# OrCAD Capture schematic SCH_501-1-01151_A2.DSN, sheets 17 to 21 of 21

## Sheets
17 P17_USB-UART_USB2ANY_JTAG: size A3
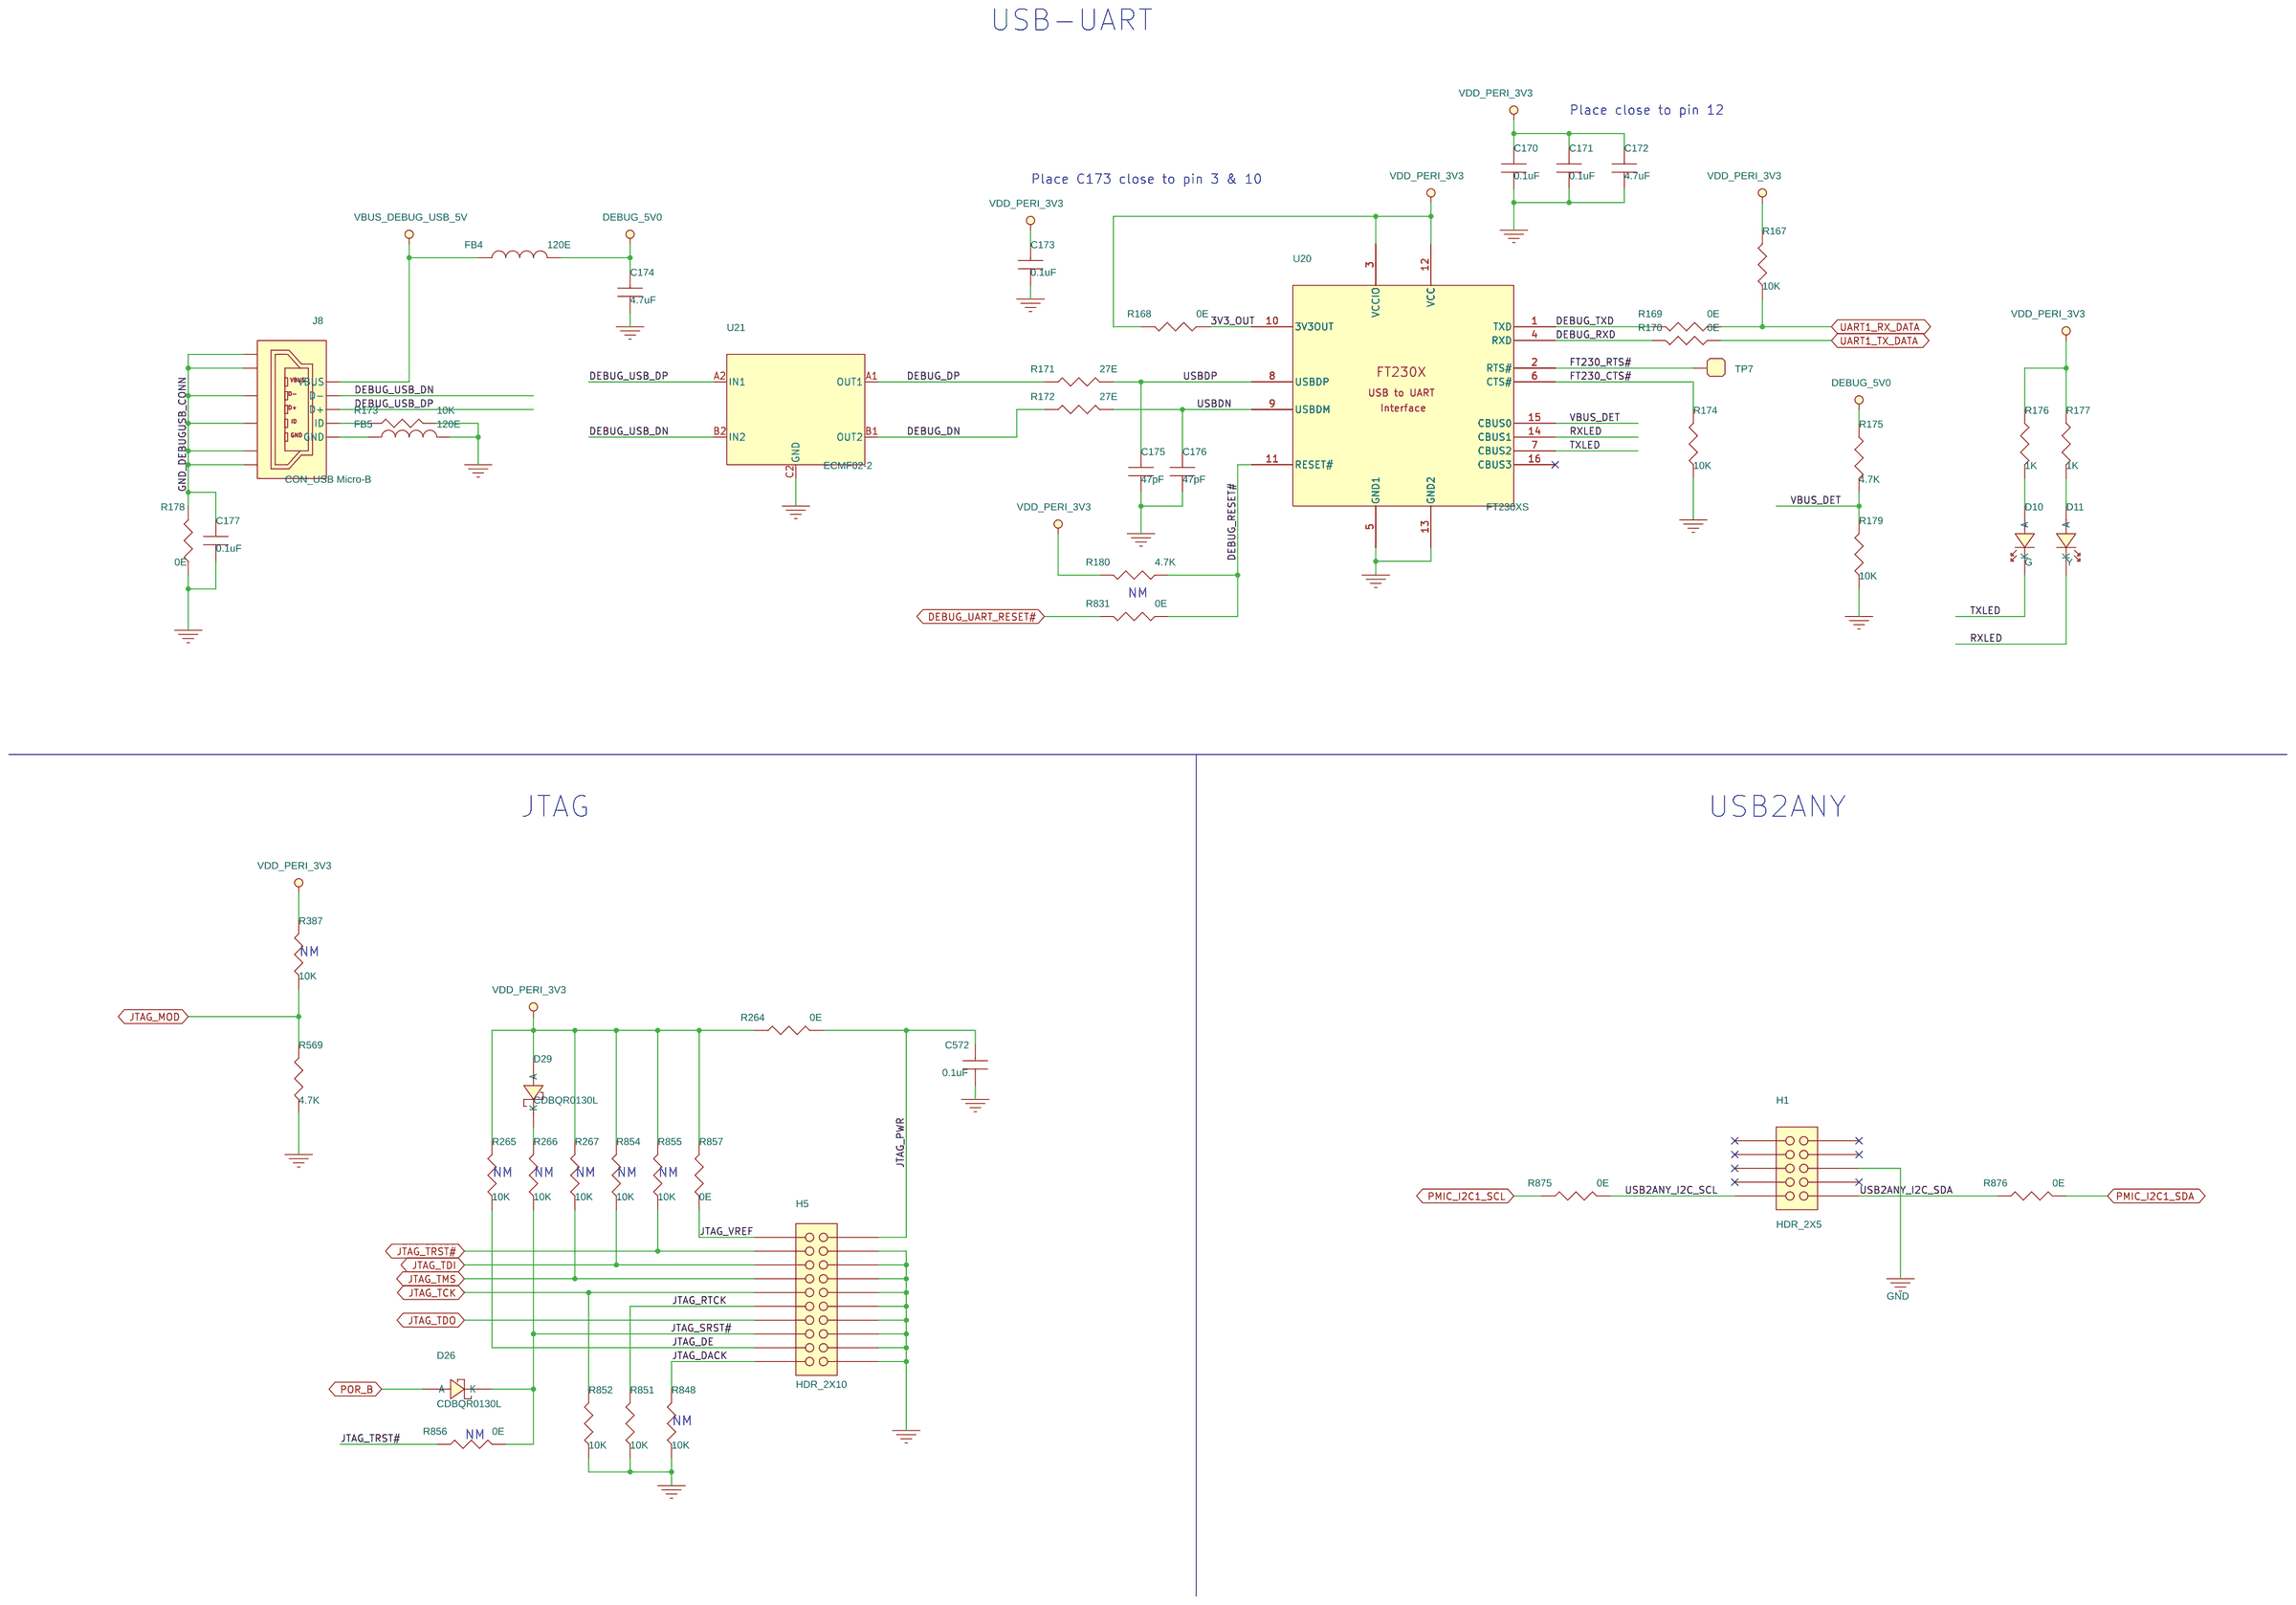
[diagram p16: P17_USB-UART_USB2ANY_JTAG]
18 P18_CURRENT SENSE: size A3
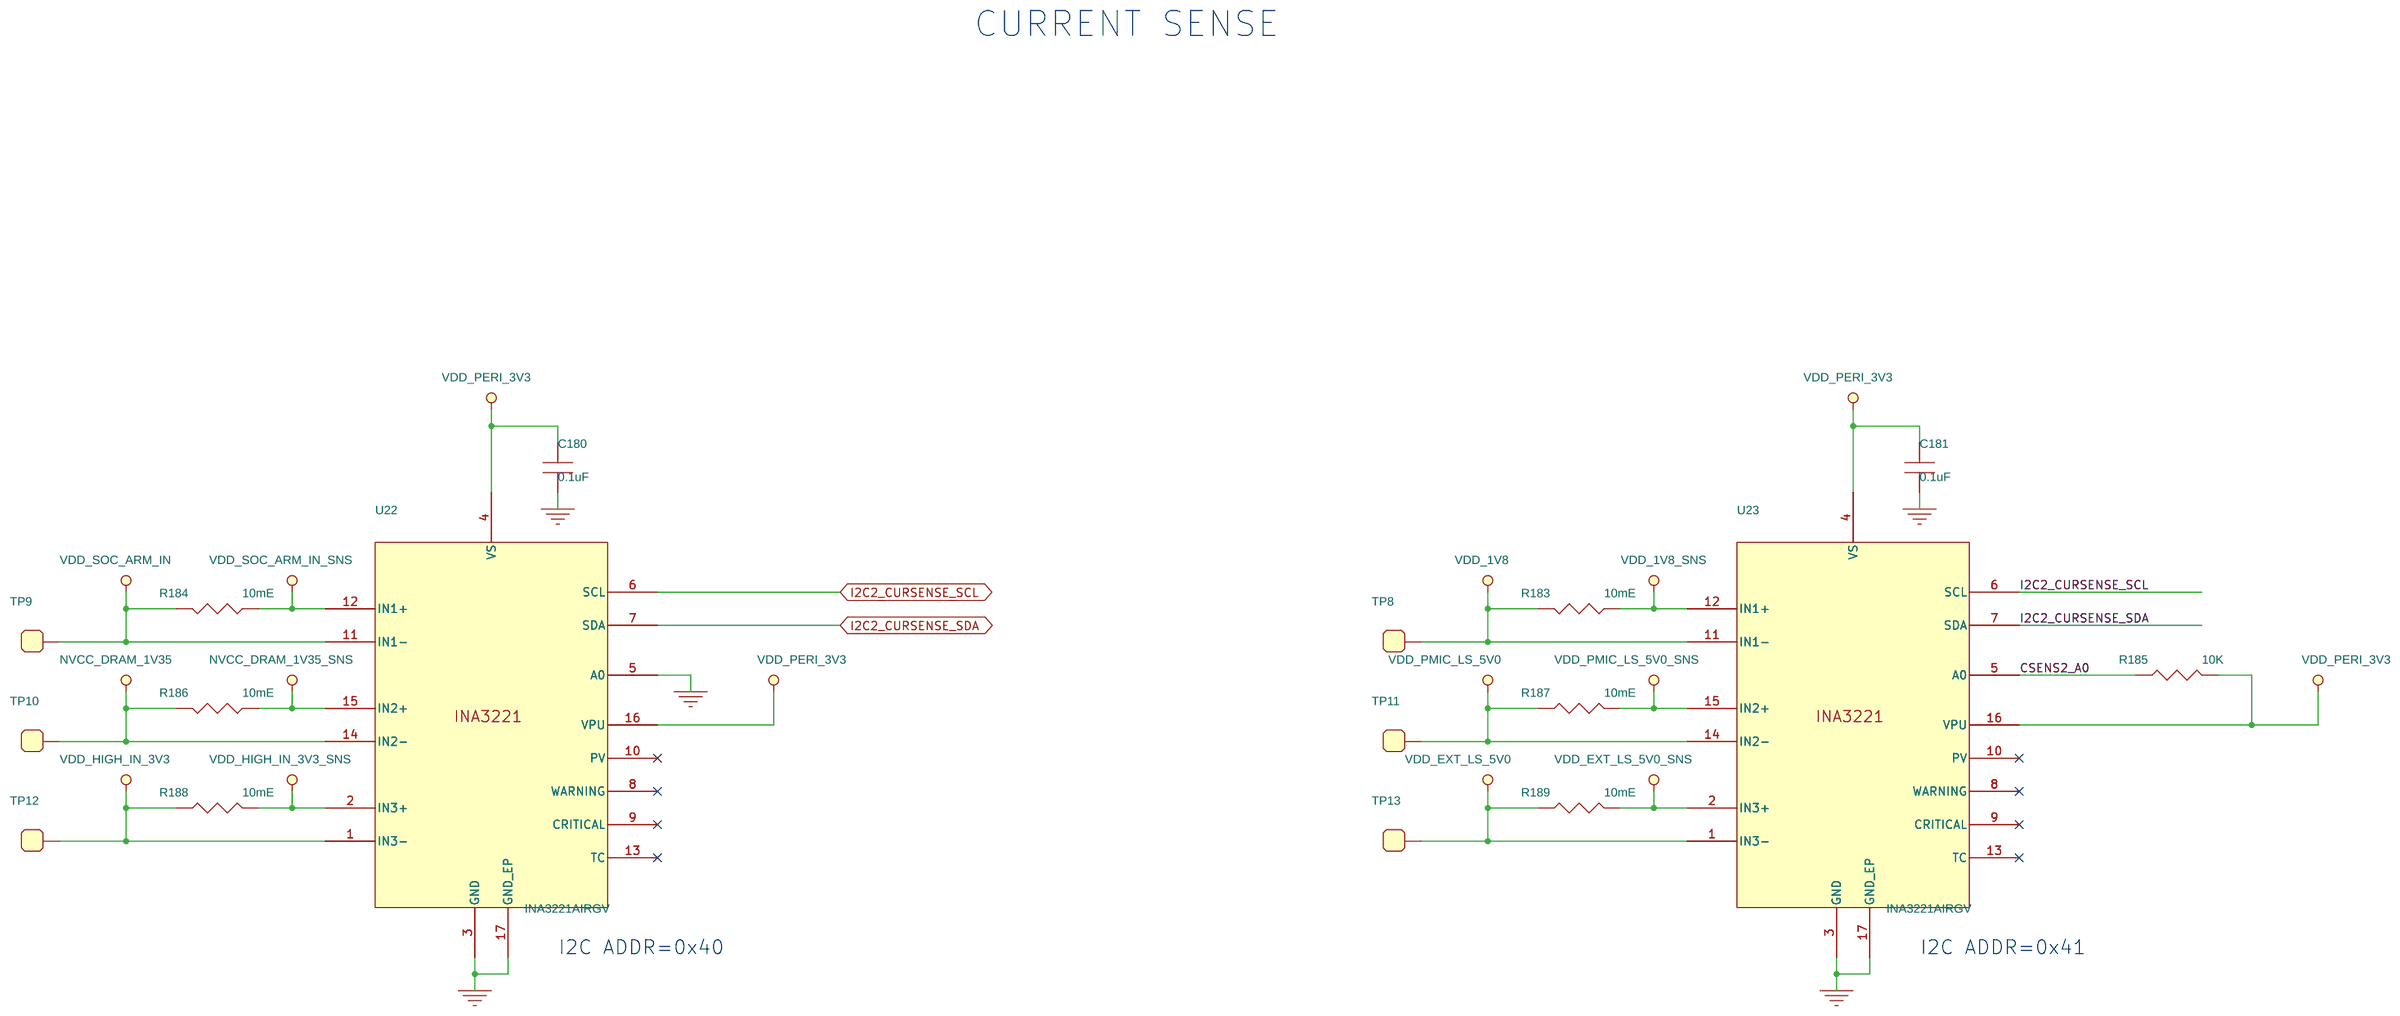
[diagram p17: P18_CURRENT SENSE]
19 P19_LCD: size A3
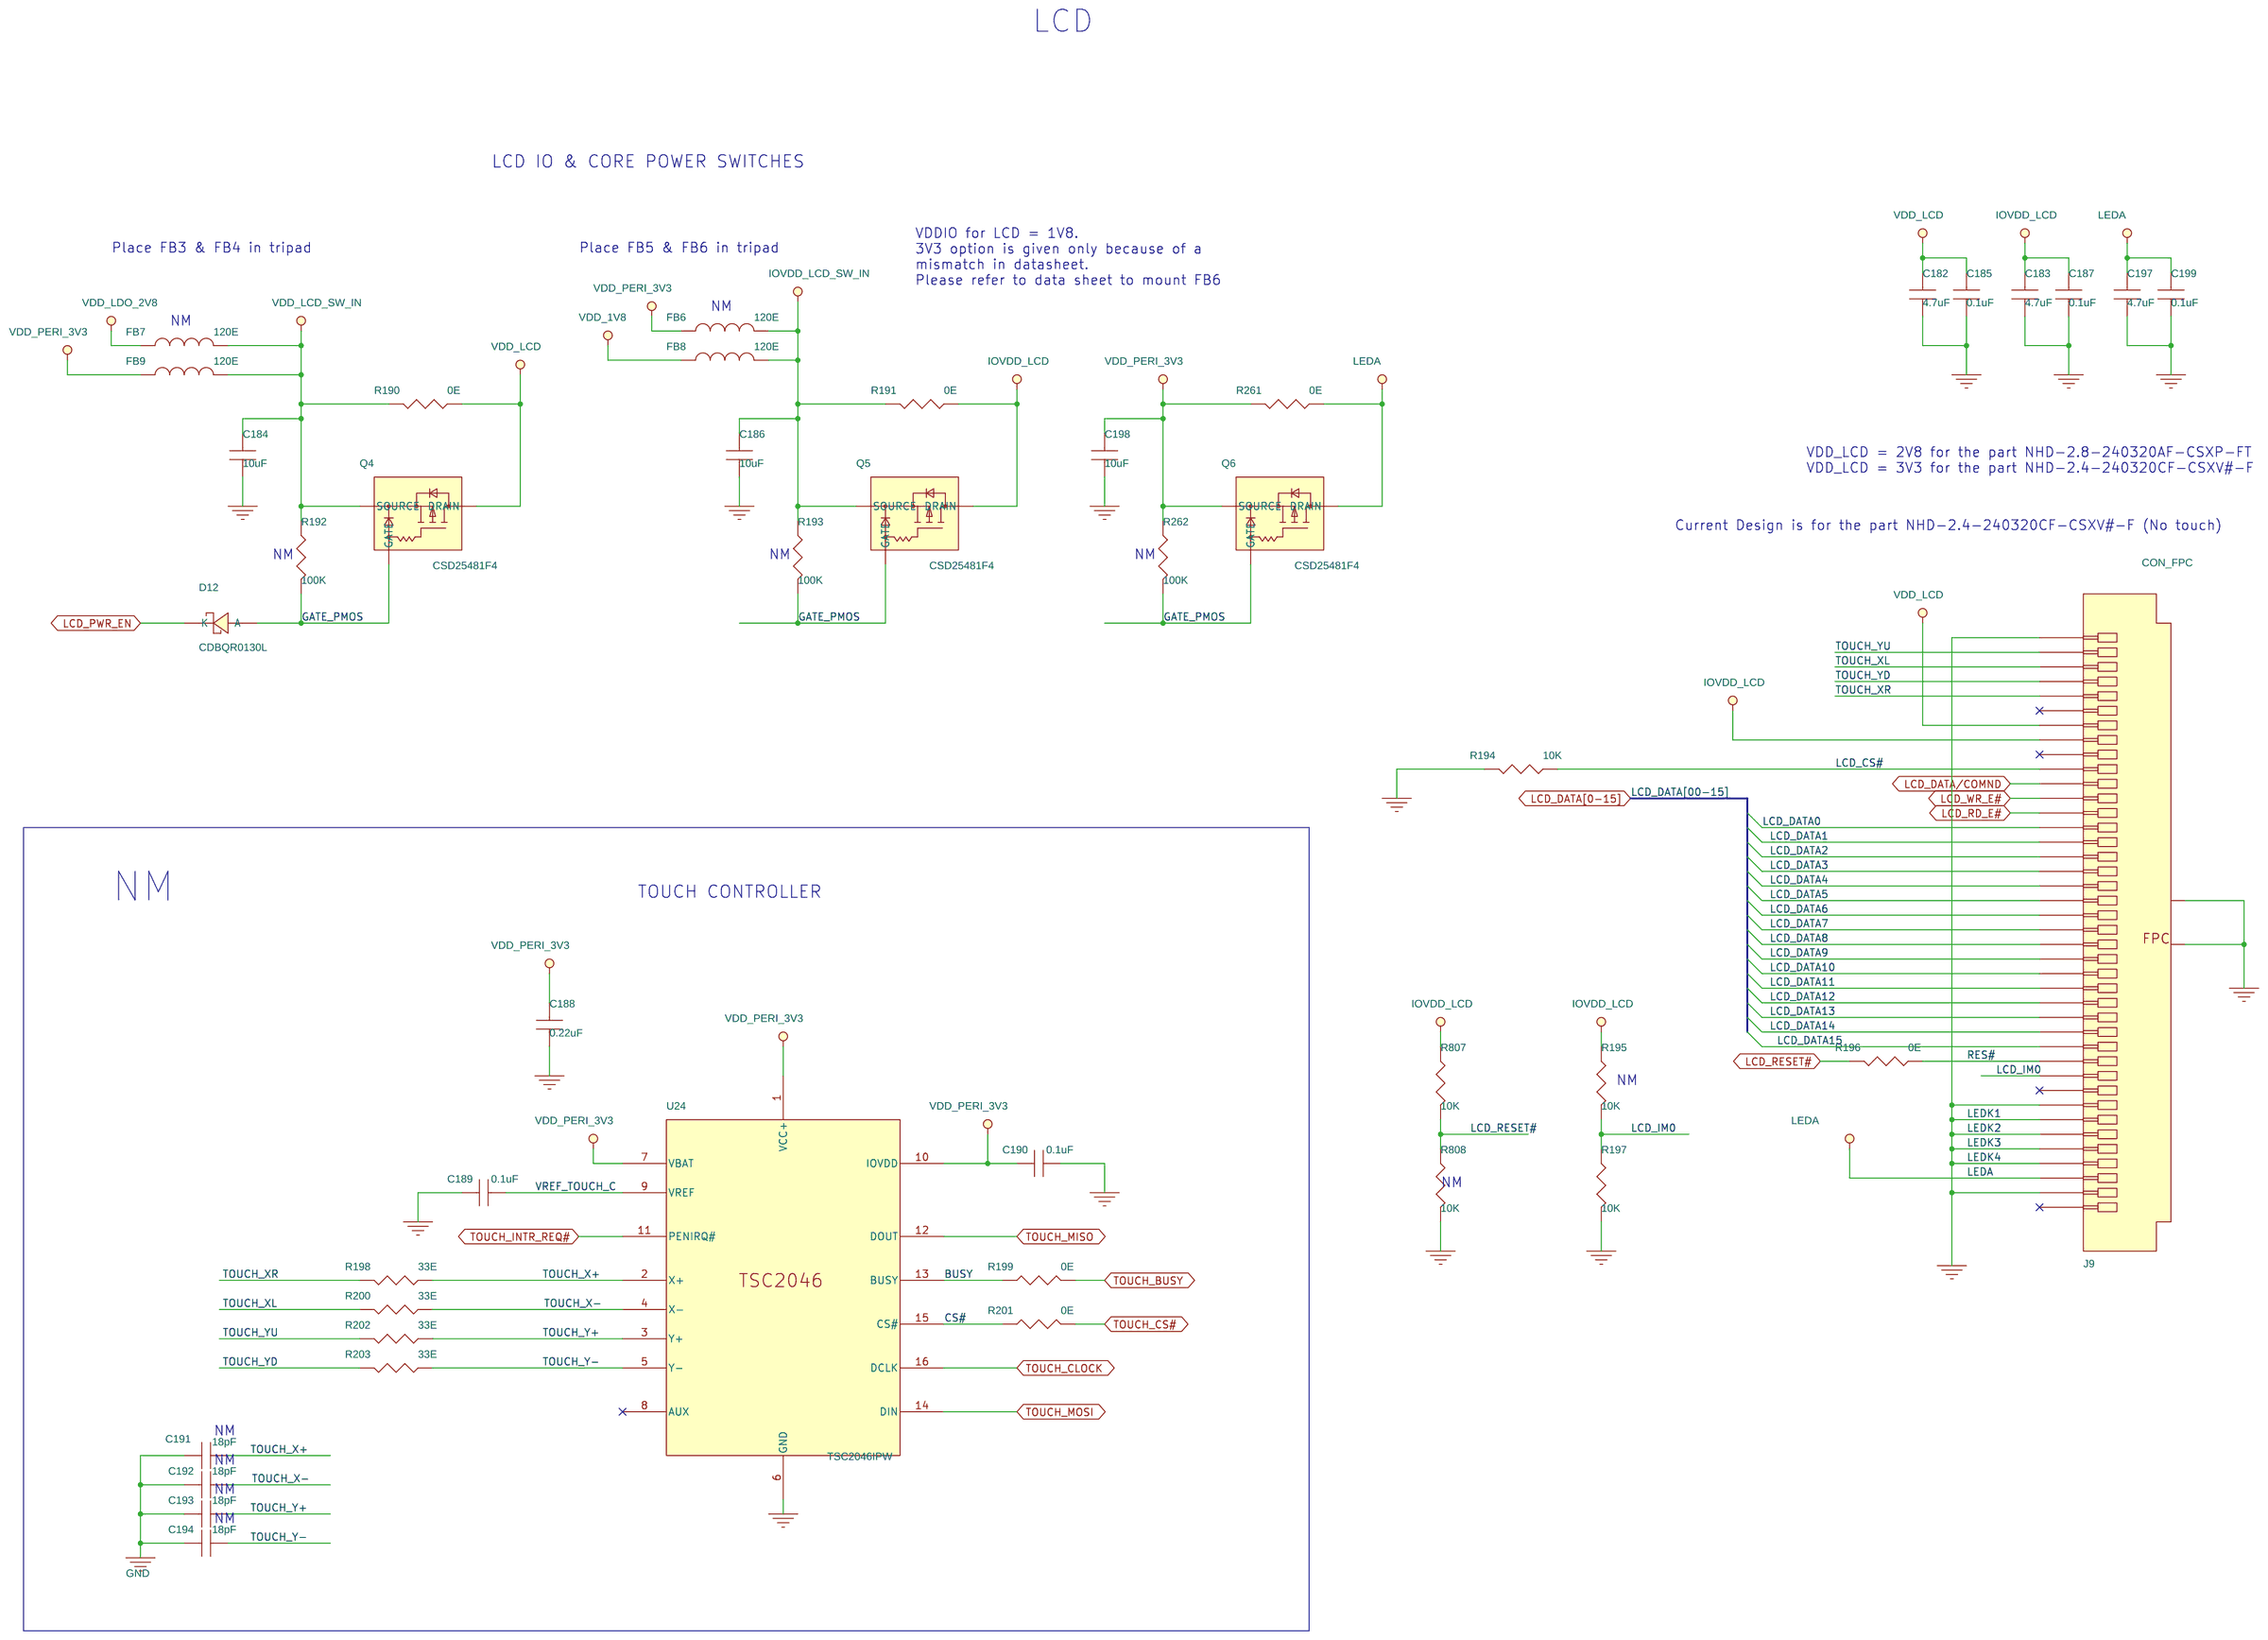
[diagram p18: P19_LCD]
20 P20_BOOT SWITCH, LED AND GPIO: size A3
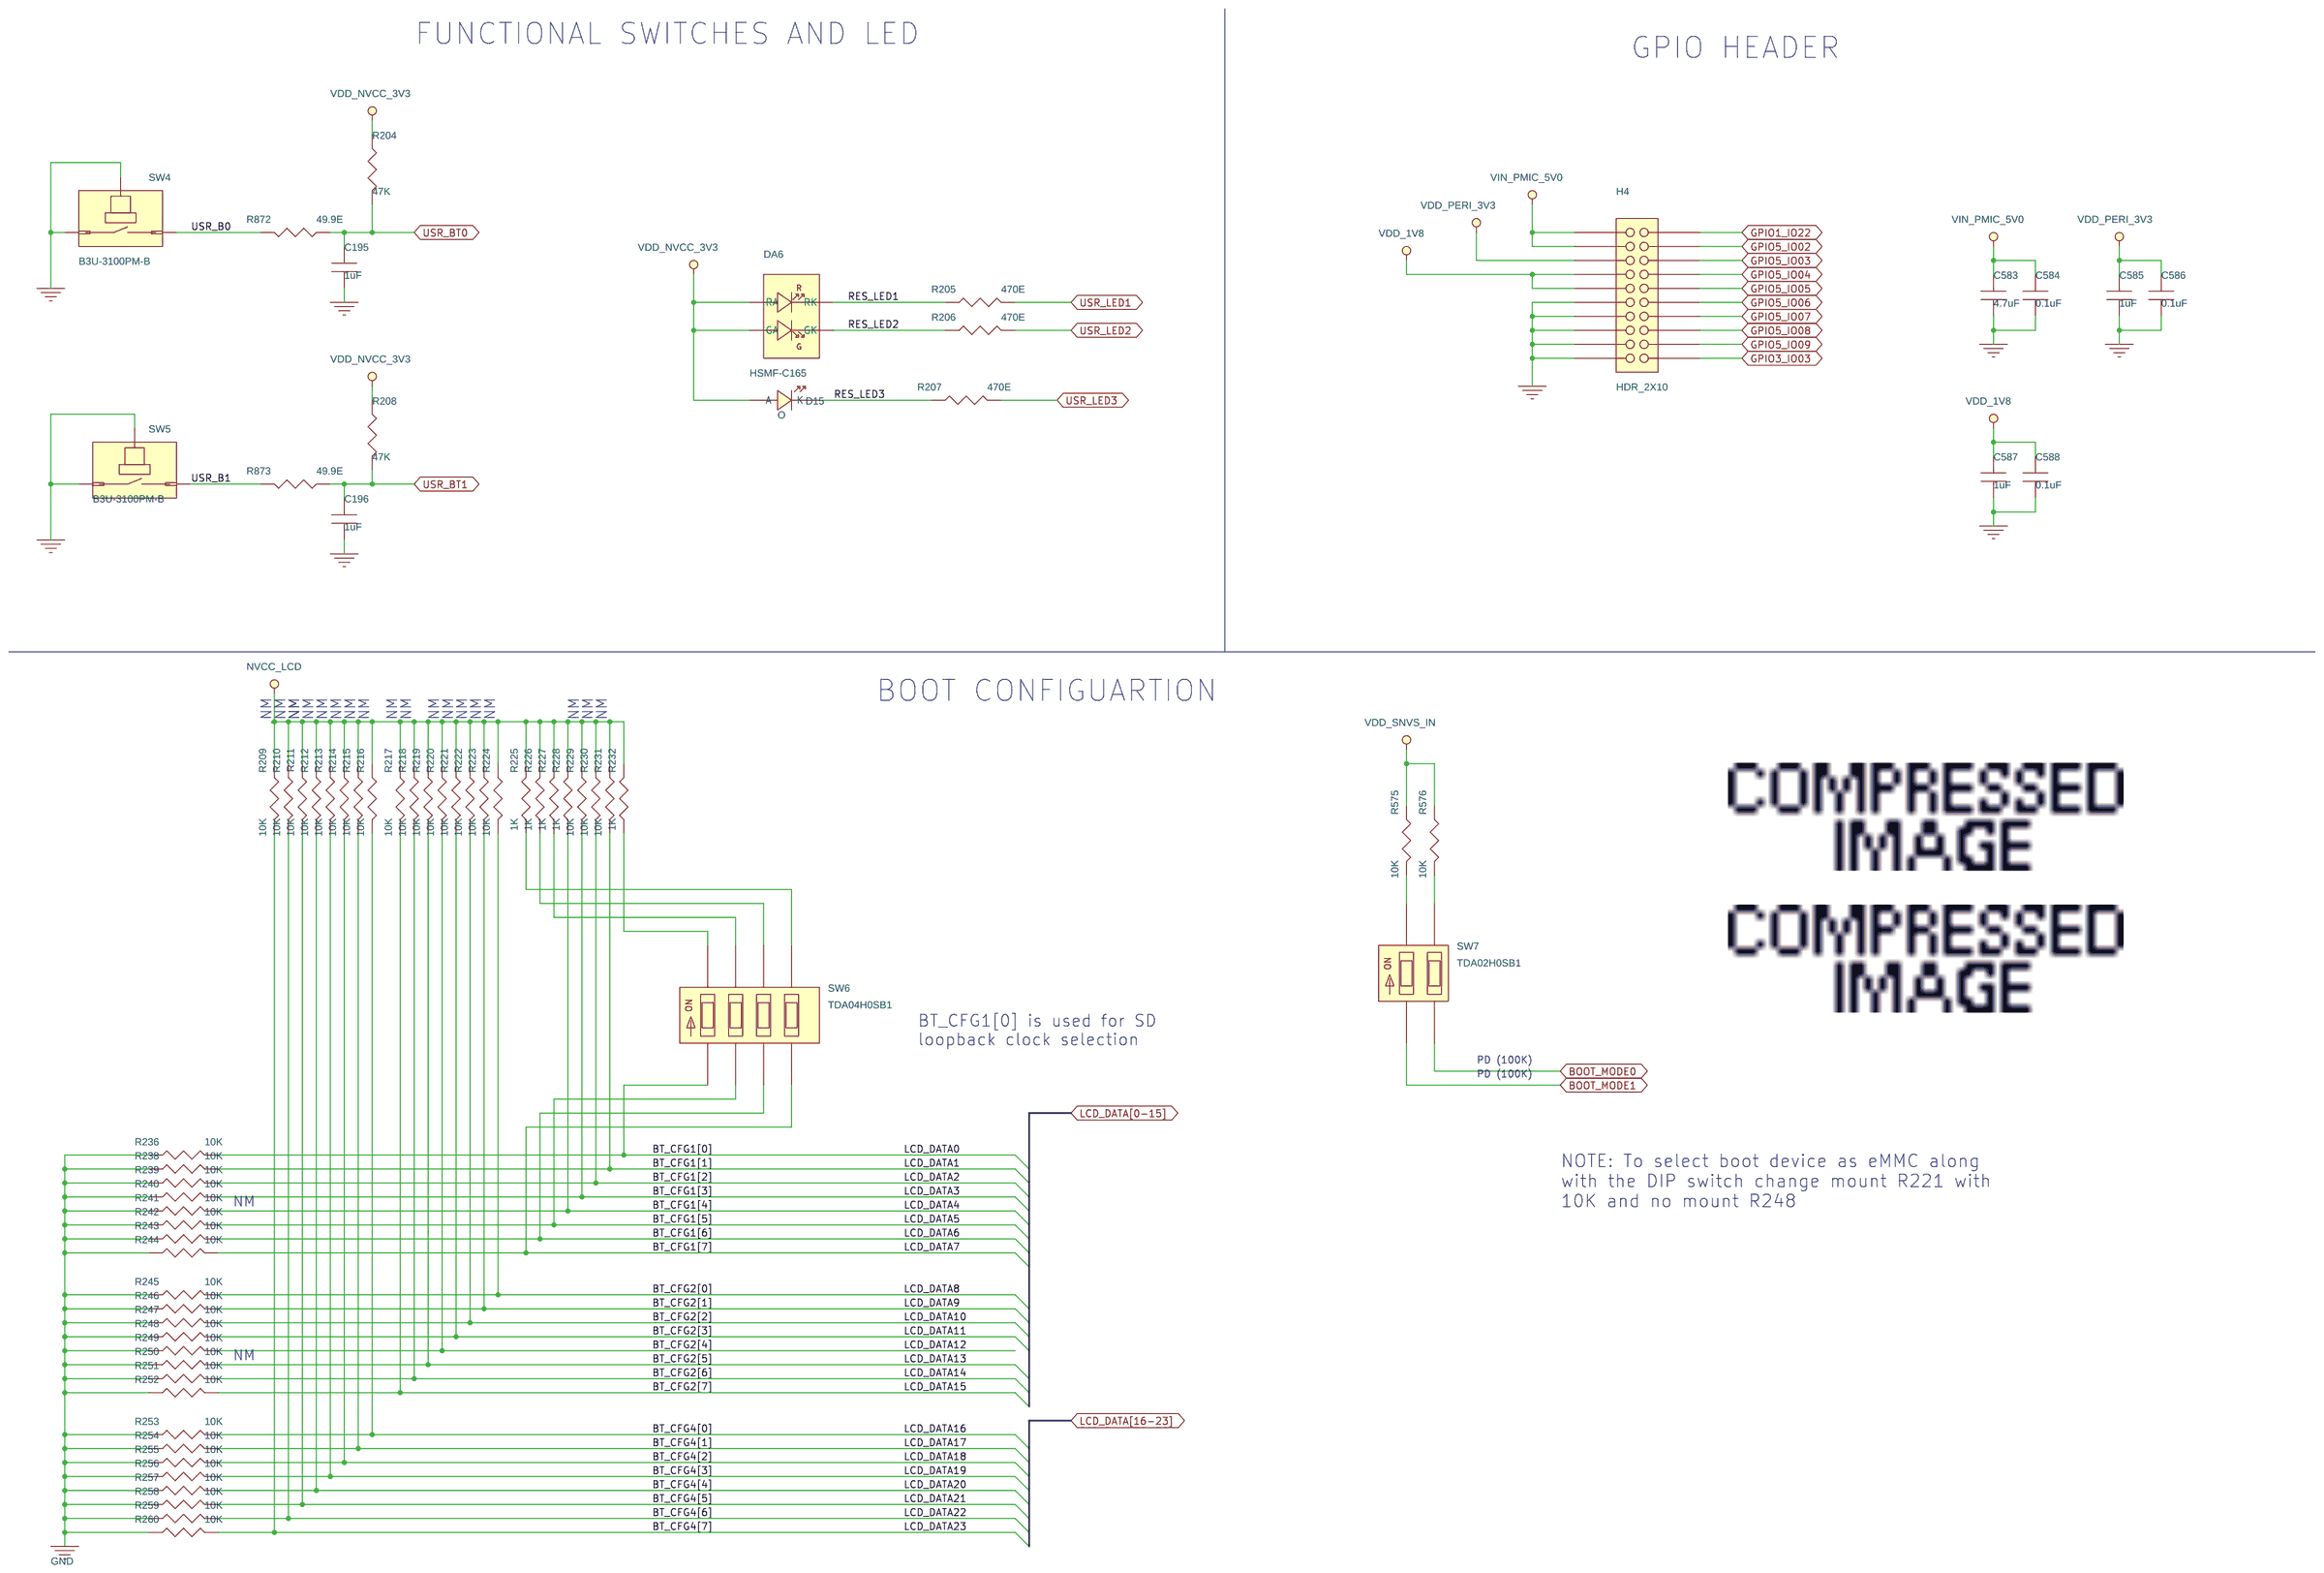
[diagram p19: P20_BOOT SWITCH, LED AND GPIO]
21 P21_MISCELLANEOUS: size A3
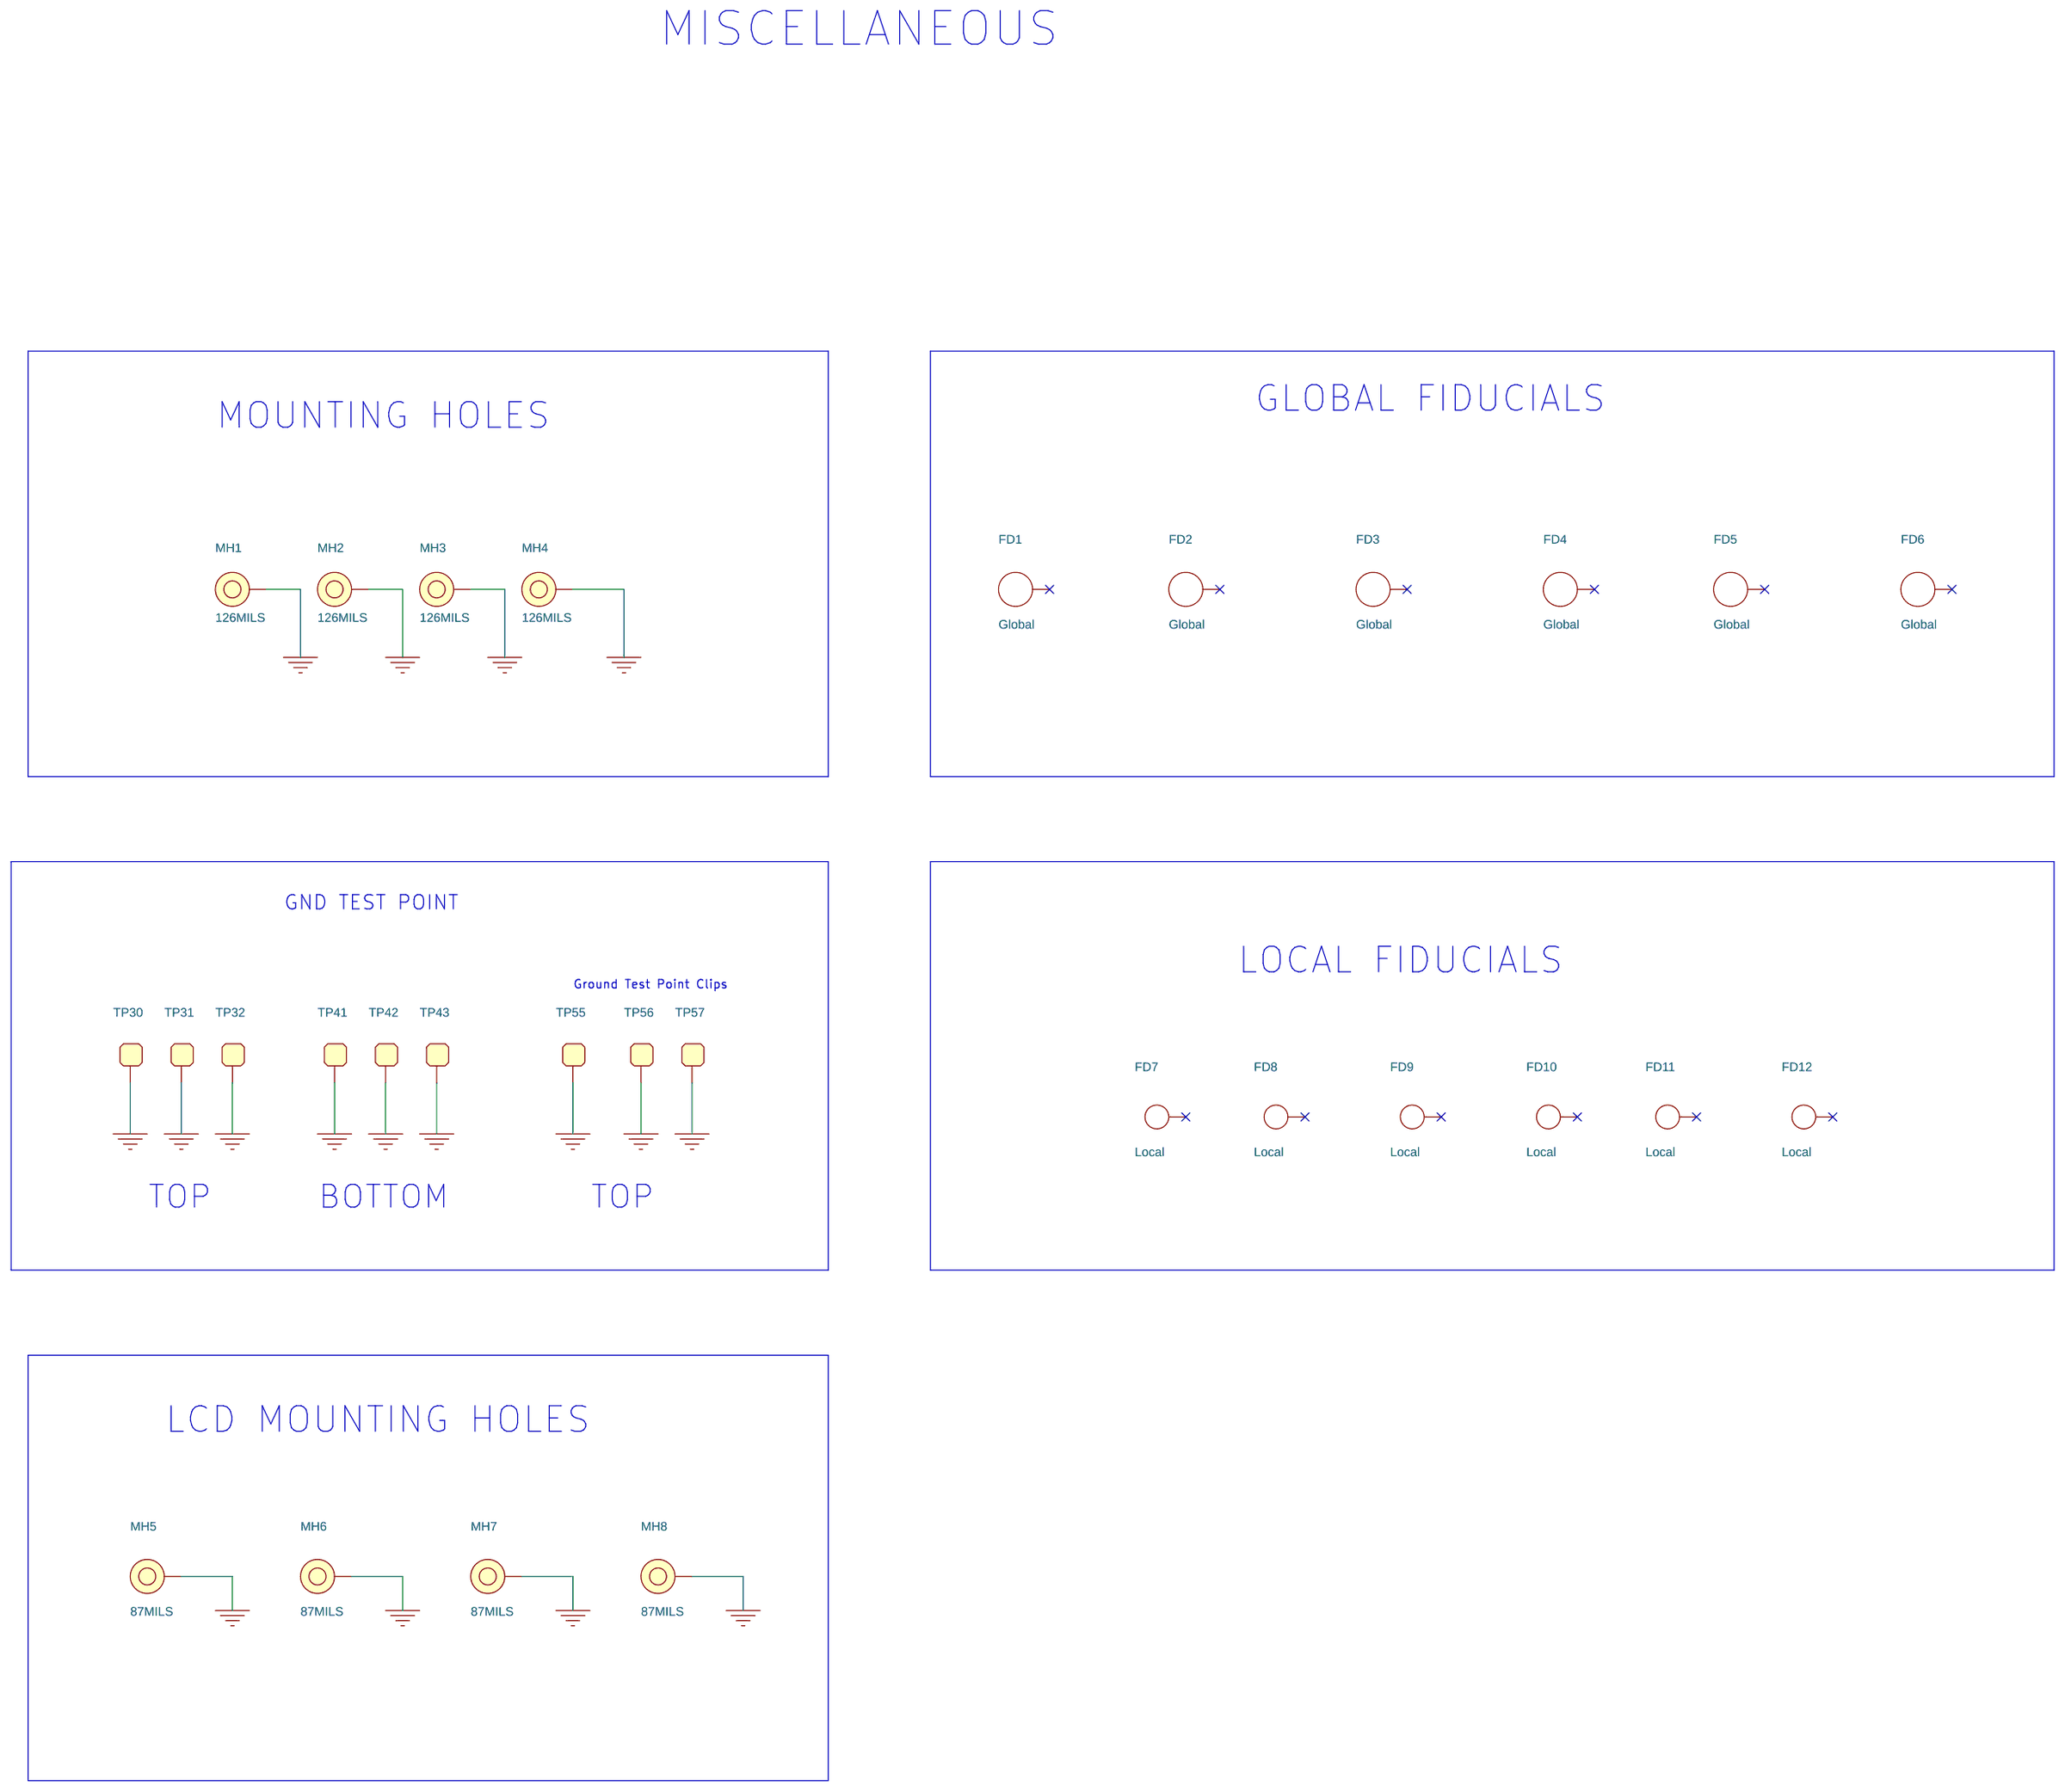
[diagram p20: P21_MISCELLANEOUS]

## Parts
sheet P17_USB-UART_USB2ANY_JTAG
C170  0.1uF  [0402]
C171  0.1uF  [0402]
C172  4.7uF  [0402]
C173  0.1uF  [0402]
C174  4.7uF  [0603]
C175  47pF  [0402]
C176  47pF  [0402]
C177  0.1uF  [0402]
C572  0.1uF  [0402]
D10  G  [LED-0603]
D11  Y  [LED-0603_C_A1]
D26  CDBQR0130L  [DIO-0402]
D29  CDBQR0130L  [DIO-0402]
FB4  120E  [0402]
FB5  120E  [0402]
H1  HDR_2X5  [CON_HDR_2X5M_2P54_SM_ST]
H5  HDR_2X10  [CON_HDR_2X10M_2P54_SM_CUST_A1]
J8  CON_USB Micro-B  [CON_USB_1X1-5F_0P65_SM_RA_D_A1]
R167  10K  [0402]
R168  0E  [0402]
R169  0E  [0402]
R170  0E  [0402]
R171  27E  [0402]
R172  27E  [0402]
R173  10K  [0402]
R174  10K  [0402]
R175  4.7K  [0402]
R176  1K  [0402]
R177  1K  [0402]
R178  0E  [0402]
R179  10K  [0402]
R180  4.7K  [0402]
R264  0E  [0402]
R265  10K  [0402]
R266  10K  [0402]
R267  10K  [0402]
R387  10K  [0402]
R569  4.7K  [0402]
R831  0E  [0402]
R848  10K  [0402]
R851  10K  [0402]
R852  10K  [0402]
R854  10K  [0402]
R855  10K  [0402]
R856  0E  [0402]
R857  0E  [0402]
R875  0E  [0402]
R876  0E  [0402]
TP7  SMD  [TP40_SMD]
U20  FT230XS  [SSOP16_0P635_5X4]
U21  ECMF02-2  [BGA5_0P4_0P83X1P23_A1]
sheet P18_CURRENT SENSE
C180  0.1uF  [0402]
C181  0.1uF  [0402]
R183  10mE  [0603]
R184  10mE  [0603]
R185  10K  [0402]
R186  10mE  [0603]
R187  10mE  [0805]
R188  10mE  [0805]
R189  10mE  [0805]
TP8  SMD  [TP40_SMD]
TP9  SMD  [TP40_SMD]
TP10  SMD  [TP40_SMD]
TP11  SMD  [TP40_SMD]
TP12  SMD  [TP40_SMD]
TP13  SMD  [TP40_SMD]
U22  INA3221AIRGV  [QFN16_0P65_4X4_EP_I_A1]
U23  INA3221AIRGV  [QFN16_0P65_4X4_EP_I_A1]
sheet P19_LCD
C182  4.7uF  [0402]
C183  4.7uF  [0402]
C184  10uF  [0402]
C185  0.1uF  [0402]
C186  10uF  [0402]
C187  0.1uF  [0402]
C188  0.22uF  [0402]
C189  0.1uF  [0402]
C190  0.1uF  [0402]
C191  18pF  [0402]
C192  18pF  [0402]
C193  18pF  [0402]
C194  18pF  [0402]
C197  4.7uF  [0402]
C198  10uF  [0402]
C199  0.1uF  [0402]
D12  CDBQR0130L  [DIO-0402]
FB6  120E  [0402]
FB7  120E  [0402]
FB8  120E  [0402]
FB9  120E  [0402]
J9  CON_FPC  [CON_FPC_1X40F_0P5_SM_RA_N_A1]
Q4  CSD25481F4  [MOSFET_0402-3L_A1]
Q5  CSD25481F4  [MOSFET_0402-3L_A1]
Q6  CSD25481F4  [MOSFET_0402-3L_A1]
R190  0E  [0402]
R191  0E  [0402]
R192  100K  [0402]
R193  100K  [0402]
R194  10K  [0402]
R195  10K  [0402]
R196  0E  [0402]
R197  10K  [0402]
R198  33E  [0402]
R199  0E  [0402]
R200  33E  [0402]
R201  0E  [0402]
R202  33E  [0402]
R203  33E  [0402]
R261  0E  [0402]
R262  100K  [0402]
R807  10K  [0402]
R808  10K  [0402]
U24  TSC2046IPW  [TSSOP16_0P65_4P4X5_F_A1]
sheet P20_BOOT SWITCH, LED AND GPIO
C195  1uF  [0402]
C196  1uF  [0402]
C583  4.7uF  [0603]
C584  0.1uF  [0402]
C585  1uF  [0402]
C586  0.1uF  [0402]
C587  1uF  [0402]
C588  0.1uF  [0402]
D15  O  [LED2_0P9_1X0P6]
DA6  HSMF-C165  [LED4_0P7_1P6X0P8]
H4  HDR_2X10  [CON_BERG_2X10M_1P27_SM_ST_A_A1]
R204  47K  [0402]
R205  470E  [0402]
R206  470E  [0402]
R207  470E  [0402]
R208  47K  [0402]
R209  10K  [0402]
R210  10K  [0402]
R211  10K  [0402]
R212  10K  [0402]
R213  10K  [0402]
R214  10K  [0402]
R215  10K  [0402]
R216  10K  [0402]
R217  10K  [0402]
R218  10K  [0402]
R219  10K  [0402]
R220  10K  [0402]
R221  10K  [0402]
R222  10K  [0402]
R223  10K  [0402]
R224  10K  [0402]
R225  1K  [0402]
R226  1K  [0402]
R227  1K  [0402]
R228  1K  [0402]
R229  10K  [0402]
R230  10K  [0402]
R231  10K  [0402]
R232  1K  [0402]
R236  10K  [0402]
R238  10K  [0402]
R239  10K  [0402]
R240  10K  [0402]
R241  10K  [0402]
R242  10K  [0402]
R243  10K  [0402]
R244  10K  [0402]
R245  10K  [0402]
R246  10K  [0402]
R247  10K  [0402]
R248  10K  [0402]
R249  10K  [0402]
R250  10K  [0402]
R251  10K  [0402]
R252  10K  [0402]
R253  10K  [0402]
R254  10K  [0402]
R255  10K  [0402]
R256  10K  [0402]
R257  10K  [0402]
R258  10K  [0402]
R259  10K  [0402]
R260  10K  [0402]
R575  10K  [0402]
R576  10K  [0402]
R872  49.9E  [0402]
R873  49.9E  [0402]
SW4  B3U-3100PM-B  [SW3_1P7_3X2P5_SM_RA_A1]
SW5  B3U-3100PM-B  [SW3_1P7_3X2P5_SM_RA_A1]
SW6  TDA04H0SB1  [SW04_1P27_6P21X6P2]
SW7  TDA02H0SB1  [SW4_1P27_3P67X6P2]
sheet P21_MISCELLANEOUS
FD1  Global  [GFD40_120]
FD2  Global  [GFD40_120]
FD3  Global  [GFD40_120]
FD4  Global  [GFD40_120]
FD5  Global  [GFD40_120]
FD6  Global  [GFD40_120]
FD7  Local  [LFD40_80]
FD8  Local  [LFD40_80]
FD9  Local  [LFD40_80]
FD10  Local  [LFD40_80]
FD11  Local  [LFD40_80]
FD12  Local  [LFD40_80]
MH1  126MILS  [MH236D126T_A1]
MH2  126MILS  [MH236D126T_A1]
MH3  126MILS  [MH236D126T_A1]
MH4  126MILS  [MH236D126T_A1]
MH5  87MILS  [MH165D87T_A1]
MH6  87MILS  [MH165D87T_A1]
MH7  87MILS  [MH165D87T_A1]
MH8  87MILS  [MH165D87T_A1]
TP30  SMD  [TP40_SMD_A1]
TP31  SMD  [TP40_SMD_A1]
TP32  SMD  [TP40_SMD_A1]
TP41  SMD  [TP40_SMD_A1]
TP42  SMD  [TP40_SMD_A1]
TP43  SMD  [TP40_SMD_A1]
TP55  SMD  [TP_3P8X2P03_SMD_A1]
TP56  SMD  [TP_3P8X2P03_SMD_A1]
TP57  SMD  [TP_3P8X2P03_SMD_A1]

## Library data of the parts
C170 C171 C173 C177 C180 C181 C185 C187 C189 C190 C199 C572 C584 C586 C588 = CAP_NP: Cap, Cer-X7R, 0.1uF, 16V, 10%, 0402; EN: 102-1-01629; KEY Number: 102-1-01629@1; Mfg: WALSIN TECHNOLOGY CORP.; Mfg Part No: 0402B104K160CT; Temperature: -55°C to +125°C
C172 C182 C183 C197 = CAP_NP: Cap, Cer-X5R, 4.7uF, 10V, 10%, 0402; EN: 102-1-02063; KEY Number: 102-1-02063@1; Mfg: TDK CORPORATION; Mfg Part No: C1005X5R1A475K050BC; Temperature: -55°C to +85°C
C174 = CAP_NP: Cap, Cer-X5R, 4.7uF, 16V, 10%, 0603; EN: 102-1-00091; FPLIST: 0603,0603_HD; KEY Number: 102-1-00091@4; Mfg: MURATA MANUFACTURING CO,LTD; Mfg Part No: GRM188R61C475KAAJD; Temperature: -55°C to +85°C
C175 C176 = CAP_NP: Cap, Cer-NPO, 47pF, 50V, 1%, 0402; EN: 102-1-00770; KEY Number: 102-1-00770@1; Mfg: AVX CORPORATION; Mfg Part No: 04025A470FAT2A; Temperature: -55°C to +125°C
D10 = DIODE_LED: LED, Single, Green, 0603; EN: 106-4-00005; KEY Number: 106-4-00005@1; Mfg: DIALIGHT; Mfg Part No: 598-8070-107F; Temperature: -30°C to +85°C
D11 = DIODE_LED: LED, Single, Yellow, 0603; EN: 106-4-00385; KEY Number: 106-4-00385@2; Mfg: OSRAM OPTO SEMICONDUCTORS; Mfg Part No: Q65111A3365; Temperature: -30°C to +85°C
D12 D26 D29 = DIODE_SCH: Diode, Schottky, 0.1A, 30V, 0.125W, 0402; EN: 106-2-00083; KEY Number: 106-2-00083@1; Mfg: COMCHIP TECHNOLOGY; Mfg Part No: CDBQR0130L-HF; Temperature: -40°C to +125°C
FB4-FB9 = FER_BEAD: F-Bead, 120E, 1.3A, SMD0402; EN: 104-1-00007; KEY Number: 104-1-00007@1; Mfg: MURATA MANUFACTURING CO,LTD; Mfg Part No: BLM15PD121SN1B; Temperature: -55°C to +125°C
H1 = HDR_2X5_10P: Conn, Berg strip, 2x5, 2.54mm, ST, SMD; EN: 201-1-00116; KEY Number: 201-1-00116@1; Mfg: SAMTEC INC; Mfg Part No: TSM-105-01-T-DV
H5 = HDR_2X10_20P: Conn, Berg strip, 2x10, 2.54mm, 3A, ST, SMD; EN: 201-1-00716; FPLIST: CON_HDR_2X10M_2P54_SM_ST_A1,CON_HDR_2X10M_2P54_SM_CUST_A1; KEY Number: 201-1-00716@1; Mfg: MOLEX; Mfg Part No: 15-91-2200; Temperature: -40°C to +105°C
J8 = CONN_USB-5X1_11P: Conn, USB Micro-B Receptacle, 1x1, RA, SMD; EN: 201-2-00519; KEY Number: 201-2-00519@1; Mfg: FCI - AMPHENOL ICC; Mfg Part No: 10118193-0001LF; Temperature: -55°C to +85°C
R167 R173 R174 R179 R185 R194 R195 R197 R209-R224 R229-R231 R236 R238-R260 R265-R267 R387 R575 R576 R807 R808 R848 R851 R852 R854 R855 = RES_v2: Res, Chip, 10K, 1/10W, 1%, AEC-Q200, 0402; EN: 101-1-00389; KEY Number: 101-1-00389@2; Mfg: PANASONIC; Mfg Part No: ERJ2RKF1002X; Temperature: -55°C to +155°C
R168-R170 R178 R190 R191 R196 R199 R201 R261 R264 R831 R856 R857 R875 R876 = RES_v2: Res, Chip, 0E, 1/16W, 1.5A, AEC-Q200, 0402; EN: 101-1-00001; KEY Number: 101-1-00001@2; Mfg: VISHAY; Mfg Part No: CRCW04020000Z0ED; Temperature: -55°C to +155°C
R171 R172 = RES_v2: Res, Chip, 27E, 1/10W, 1%, AEC-Q200, 0402; EN: 101-1-03414; KEY Number: 101-1-03414@1; Mfg: KOA SPEER ELECTRONICS, INC.; Mfg Part No: RK73H1ETTP27R0F; Temperature: -55°C to +155°C
R175 R180 R569 = RES_v2: Res, Chip, 4.7K, 1/16W, 1%, 0402; EN: 101-1-03446; KEY Number: 101-1-03446@2; Mfg: WALSIN TECHNOLOGY CORP.; Mfg Part No: WR04X4701FTL; Temperature: -55°C to +155°C
R176 R177 R225-R228 R232 = RES_v2: Res, Chip, 1K, 1/16W, 5%, 0402; EN: 101-1-02769; KEY Number: 101-1-02769@4; Mfg: WALSIN TECHNOLOGY CORP.; Mfg Part No: WR04X102JTL; Temperature: -55°C to +155°C
TP7-TP13 = TEST_POINT_SMD: Testpoint, Pad=1mm, SM=1.3mm, SMD; EN: 666-1-00008; KEY Number: 666-1-00008@1; Mfg: NA; Mfg Part No: 666-1-00008
U20 = IC_FT230X_SSOP-16P: IC, FT230, USB to UART Interface, SSOP-16; EN: 301-0-00404; KEY Number: 301-0-00404@1; Mfg: FTDI CHIP
U21 = IC_FIL_COM-MODE_WLCSP-5P: IC, ECMF02-2, Dual line CM Filter with ESD Protection, 5GHz, WLCSP-5P; EN: 301-0-01102; KEY Number: 301-0-01102@1; Mfg: ST MICROELECTRONICS; Mfg Part No: ECMF02-2BF3; Temperature: -30°C to +85°C
R183 R184 R186 = RES_v2: Res, I-Sense, 10mE, 1/4W, 1%, 0603; EN: 101-3-00046; KEY Number: 101-3-00046@2; Mfg: WALSIN TECHNOLOGY CORP.; Mfg Part No: WW06CR010FTL; Temperature: -55°C to +125°C
R187-R189 = RES_v2: Res, I-Sense, 10mE, 1/2W, 1%, 0805; EN: 101-3-00104; KEY Number: 101-3-00104@2; Mfg: BOURNS INC; Mfg Part No: CFN0805-FX-R010ELF; Temperature: -55°C to +155°C
U22 U23 = IC_INA3221_VQFN-16P_EP_A1: IC, INA3221, 3-Channel, High side Current/Voltage Monitor with I2C, VQFN-16; EN: 301-0-02543; KEY Number: 301-0-02543@1; Mfg: TEXAS INSTRUMENTS; Mfg Part No: INA3221AIRGVR; Temperature: -40°C to +125°C
C184 C186 C198 = CAP_NP: Cap, Cer-X5R, 10uF, 10V,  20%, 0402; EN: 102-1-01803; KEY Number: 102-1-01803@6; Mfg: MURATA MANUFACTURING CO,LTD; Mfg Part No: GRM155R61A106ME11D; Temperature: -55°C to +85°C
C188 = CAP_NP: Cap, Cer-X5R, 0.22uF, 10V, 10%, 0402; EN: 102-1-00210; FPLIST: 0402,0402_CIR; KEY Number: 102-1-00210@1; Mfg: MURATA MANUFACTURING CO,LTD; Mfg Part No: GRM155R61A224KE19D; Temperature: -55°C to +85°C
C191-C194 = CAP_NP: Cap, Cer-NPO, 18pF, 50V, 5%, 0402; EN: 102-1-01806; KEY Number: 102-1-01806@2; Mfg: WALSIN TECHNOLOGY CORP.; Mfg Part No: 0402N180J500CT; Temperature: -55°C to +125°C
J9 = CONN_FPC-40_42P: Conn, FPC, Receptacle, 1x40, 0.5mm, 0.5A, Bottom Contact, RA, SMD; EN: 201-2-00121; KEY Number: 201-2-00121@1; Mfg: MOLEX; Mfg Part No: 54132-4062
Q4-Q6 = TRANS_PMOS-ENX1_3P_C: Transistor, P-MOSFET, 20V, 2.5A, Vgs=12V, 0.5W, 0402; EN: 107-2-00200; KEY Number: 107-2-00200@1; Mfg: TEXAS INSTRUMENTS; Mfg Part No: CSD25481F4T; Temperature: -55°C to +150°C
R192 R193 R262 = RES_v2: Res, Chip, 100K, 1/16W, 1%, 0402; EN: 101-1-00485; KEY Number: 101-1-00485@3; Mfg: WALSIN TECHNOLOGY CORP.; Mfg Part No: WR04X1003FTL; Temperature: -55°C to +155°C
R198 R200 R202 R203 = RES_v2: Res, Chip, 33E, 1/16W, 1%, 0402; EN: 101-1-03680; KEY Number: 101-1-03680@2; Mfg: WALSIN TECHNOLOGY CORP.; Mfg Part No: WR04X33R0FTL; Temperature: -55°C to +155°C
U24 = IC_TSC2046_TSSOP-16P_A1: IC, TSC2046, Touch Screen Controller, TSSOP-16; EN: 301-0-02528; KEY Number: 301-0-02528@1; Mfg: TEXAS INSTRUMENTS; Mfg Part No: TSC2046IPWR; Temperature: -40°C to +85°C
C195 C196 C585 C587 = CAP_NP: Cap, Cer-X5R, 1uF, 16V, 10%, 0402; EN: 102-1-01745; KEY Number: 102-1-01745@3; Mfg: AVX CORPORATION; Mfg Part No: 0402YD105KAT2A; Temperature: -55°C to +85°C
C583 = CAP_NP: Cap, Cer-X5R, 4.7uF, 16V, 10%, 0603; EN: 102-1-00091; KEY Number: 102-1-00091@4; Mfg: MURATA MANUFACTURING CO,LTD; Mfg Part No: GRM188R61C475KAAJD; Temperature: -55°C to +85°C
D15 = DIODE_LED_A: LED, Single, Orange, SMD; EN: 106-4-00084; KEY Number: 106-4-00084@1; Mfg: ROHM; Mfg Part No: SML-P12DTT86; Temperature: -40°C to +85°C
DA6 = DIODE_NETX2_LED-GR_4P: LED, Single, (Green/Red), SMD0603; EN: 106-4-00053; KEY Number: 106-4-00053@1; Mfg: AVAGO TECHNOLOGIES; Temperature: -40°C to +85°C
H4 = HDR_2X10_20P: Conn, Berg strip, Male, 2x10, 1.27mm, 1A, ST, SMD; EN: 201-1-01863; KEY Number: 201-1-01863@1; Mfg: HARWIN; Mfg Part No: M50-3601042R; Temperature: -40°C to +105°C
R204 R208 = RES_v2: Res, Chip, 47K, 1/16W, 1%, 0402; EN: 101-1-03402; KEY Number: 101-1-03402@2; Mfg: WALSIN TECHNOLOGY CORP.; Mfg Part No: WR04X4702FTL; Temperature: -55°C to +155°C
R205-R207 = RES_v2: Res, Chip, 470E, 1/16W, 1%, 100ppm/degC, 0402; EN: 101-1-03571; FPLIST: 0402,0402_HD; KEY Number: 101-1-03571@1; Mfg: VISHAY; Mfg Part No: CRCW0402470RFK; Temperature: -55°C to +155°C
R872 R873 = RES_v2: Res, Chip, 49.9E, 1/16W, 1%, AEC-Q200, 0402; EN: 101-1-04432; KEY Number: 101-1-04432@1; Mfg: VISHAY; Mfg Part No: CRCW040249R9FKED; Temperature: -55°C to +155°C
SW4 SW5 = SWITCH_PUSH-2_3P_A: Switch, Tactile, SPST-NO, 12V, 50mA, with Boss, RA, SMD; EN: 205-1-00128; KEY Number: 205-1-00128@1; Mfg: OMRON CORP.; Temperature: -25°C to +70°C
SW6 = SWITCH_DIPX4_8P_B: Switch, DIP, 4 Position, 25mA, Vertical,  SMD; EN: 205-1-00023; KEY Number: 205-1-00023@1; Mfg: C&K COMPONENTS
SW7 = SWITCH_DIPX2_4P_B: Switch, DIP, 2 Position, 25mA, Vertical, SMD; EN: 205-1-00041; KEY Number: 205-1-00041@1; Mfg: C&K COMPONENTS; Temperature: -40°C to +85°C
FD1-FD6 = MECH_FID_G: Fiducial, Global, Pad=1mm, SM=3mm; EN: 666-1-00002; KEY Number: 666-1-00002@1; Mfg: NA; Mfg Part No: 666-1-00002; Temperature: NA
FD7-FD12 = MECH_FID_L: Fiducial, Local, Pad=1mm, SM=2mm; EN: 666-1-00001; KEY Number: 666-1-00001@1; Mfg: NA; Mfg Part No: 666-1-00001; Temperature: NA
MH1-MH4 = MECH_MH_PL: MH, PTH, Pad=6mm, Via=3.2mm; EN: 666-1-00157; KEY Number: 666-1-00157@1; Mfg: NA; Mfg Part No: 666-1-00157; Temperature: NA
MH5-MH8 = MECH_MH_PL: MH, PTH, Pad=4.2mm, Via=2.2mm; EN: 666-1-00336; KEY Number: 666-1-00336@1; Mfg: NA; Mfg Part No: 666-1-00336; Temperature: NA
TP30-TP32 TP41-TP43 = TEST_POINT_SMD: Testpoint, Pad=1mm, SM=1.18mm, SMD; EN: 666-1-00186; KEY Number: 666-1-00186@1; Mfg: NA; Mfg Part No: 666-1-00186
TP55-TP57 = TEST_POINT_SMD: Testpoint, Pad=3.8x2.03mm, SM=4x2.18mm, SMD; EN: 401-1-01241; KEY Number: 401-1-01241@1; Mfg: KEYSTONE ELECTRONICS; Mfg Part No: 5019; Temperature: NA

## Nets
3V3_OUT: R168.2 U20.10(3V3OUT)
GND: C170.2 C171.2 C172.2 C173.2 C174.2 C175.2 C176.2 C177.2 C180.2 C181.2 C182.2 C183.2 C184.2 C185.2 C186.2 C187.2 C188.2 C189.1 C190.2 C191.1 C192.1 C193.1 C194.1 C195.2 C196.2 C197.2 C198.2 C199.2 C572.2 C583.2 C584.2 C585.2 C586.2 C587.2 C588.2 FB5.2 H1.6 H4.11 H4.13 H4.15 H4.17 H4.19 H5.4 H5.6 H5.8 H5.10 H5.12 H5.14 H5.16 H5.18 H5.20 J9.2 J9.4 J9.5 J9.6 J9.7 J9.8 J9.40 J9.M1 J9.M2 MH1.1 MH2.1 MH3.1 MH4.1 MH5.1 MH6.1 MH7.1 MH8.1 R173.2 R174.1 R178.2 R179.1 R194.2 R197.2 R236.1 R238.1 R239.1 R240.1 R241.1 R242.1 R243.1 R244.1 R245.1 R246.1 R247.1 R248.1 R249.1 R250.1 R251.1 R252.1 R253.1 R254.1 R255.1 R256.1 R257.1 R258.1 R259.1 R260.1 R569.1 R808.2 R848.1 R851.1 R852.1 SW4.1 SW4.3 SW5.1 SW5.3 TP30.1 TP31.1 TP32.1 TP41.1 TP42.1 TP43.1 TP55.1 TP56.1 TP57.1 U20.5(GND1) U20.13(GND2) U21.C2(GND) U22.3(GND) U22.5(A0) U22.17(GND_EP) U23.3(GND) U23.17(GND_EP) U24.6(GND) ; also on sheet 3 4 5 6 7 8 9 10 11 12 13 14 15 16
GND_DEBUGUSB_CONN: C177.1 J8.S1 J8.S2 J8.S3 J8.S4 J8.S5 J8.S6 R178.1
VBUS_DEBUG_USB_5V: FB4.1 J8.1(VBUS)
VBUS_DET: R175.2 R179.2 U20.15(CBUS0)
VDD_1V8: C587.1 C588.1 FB8.1 H4.7 H4.9 R183.2 TP8.1 U23.11(IN1-) ; also on sheet 5 8 11 12
VDD_1V8_SNS: R183.1 U23.12(IN1+) ; also on sheet 4
VDD_EXT_LS_5V0: R189.1 TP13.1 U23.1(IN3-) ; also on sheet 5 16
VDD_EXT_LS_5V0_SNS: R189.2 U23.2(IN3+) ; also on sheet 5
VDD_HIGH_IN_3V3: R188.1 TP12.1 U22.1(IN3-) ; also on sheet 4 5 6
VDD_HIGH_IN_3V3_SNS: R188.2 U22.2(IN3+) ; also on sheet 4
VDD_LCD: C182.1 C185.1 J9.34 Q4.3(DRAIN) R190.2
VDD_LCD_BCKLIGHT: C197.1 C199.1 J9.3 Q6.3(DRAIN) R261.2
VDD_LCD_SW_IN: C184.1 FB7.2 FB9.2 Q4.2(SOURCE) R190.1 R192.1
VDD_LDO_2V8: FB7.1 ; also on sheet 4
VDD_NVCC_3V3: D15.1(A) DA6.1(GA) DA6.2(RA) R204.1 R208.1 ; also on sheet 4 8 9 10 16
VDD_PERI_3V3: C170.1 C171.1 C172.1 C173.1 C180.1 C181.1 C188.1 C190.1 C198.1 C585.1 C586.1 D29.2(A) FB6.1 FB9.1 H4.5 Q6.2(SOURCE) R167.2 R168.1 R176.1 R177.1 R180.2 R185.2 R261.1 R262.1 R264.1 R265.2 R267.2 R387.2 R854.2 R855.2 R857.2 U20.3(VCCIO) U20.12(VCC) U22.4(VS) U22.16(VPU) U23.4(VS) U23.16(VPU) U24.1(VCC+) U24.7(VBAT) U24.10(IOVDD) ; also on sheet 5 11 12 13 14 16
VDD_PMIC_LS_5V0: R187.1 TP11.1 U23.14(IN2-) ; also on sheet 5 9 16
VDD_PMIC_LS_5V0_SNS: R187.2 U23.15(IN2+) ; also on sheet 4
VDD_SNVS_IN: R575.1 R576.1 ; also on sheet 4 5 6 10
VDD_SOC_ARM_IN: R184.2 TP9.1 U22.11(IN1-) ; also on sheet 4 6
VDD_SOC_ARM_IN_SNS: R184.1 U22.12(IN1+) ; also on sheet 4
VIN_PMIC_5V0: C583.1 C584.1 H4.1 H4.3 ; also on sheet 3 4 5
BOOT_MODE0: SW7.2 ; also on sheet 10
BOOT_MODE1: SW7.1 ; also on sheet 10
BUSY: R199.2 U24.13(BUSY)
CS#: R201.2 U24.15(CS#)
CSENS2_A0: R185.1 U23.5(A0)
DEBUG_5V0: C174.1 FB4.2 R175.1
DEBUG_DN: R172.1 U21.B1(OUT2)
DEBUG_DP: R171.1 U21.A1(OUT1)
DEBUG_RESET#: R180.1 R831.2 U20.11(RESET#)
DEBUG_RXD: R170.1 U20.4(RXD)
DEBUG_TXD: R169.1 U20.1(TXD)
DEBUG_UART_RESET#: R831.1 ; also on sheet 9
DEBUG_USB_DN: J8.2(D-) U21.B2(IN2)
DEBUG_USB_DP: J8.3(D+) U21.A2(IN1)
FT230_CTS#: R174.2 U20.6(CTS#)
FT230_RTS#: TP7.1 U20.2(RTS#)
GATE_PMOS: D12.2(A) Q4.1(GATE) Q5.1(GATE) Q6.1(GATE) R192.2 R193.2 R262.2
GPIO1_IO22: H4.2 ; also on sheet 10
GPIO3_IO03: H4.20 ; also on sheet 8
GPIO5_IO02: H4.4 ; also on sheet 10
GPIO5_IO03: H4.6 ; also on sheet 10
GPIO5_IO04: H4.8 ; also on sheet 10
GPIO5_IO05: H4.10 ; also on sheet 10
GPIO5_IO06: H4.12 ; also on sheet 10
GPIO5_IO07: H4.14 ; also on sheet 10
GPIO5_IO08: H4.16 ; also on sheet 10
GPIO5_IO09: H4.18 ; also on sheet 10
I2C2_CURSENSE_SCL: U22.6(SCL) U23.6(SCL) ; also on sheet 10
I2C2_CURSENSE_SDA: U22.7(SDA) U23.7(SDA) ; also on sheet 10
IOVDD_LCD: C183.1 C187.1 J9.33 Q5.3(DRAIN) R191.2 R195.1 R807.1
IOVDD_LCD_SW_IN: C186.1 FB6.2 FB8.2 Q5.2(SOURCE) R191.1 R193.1
JTAG_DACK: H5.19 R848.2
JTAG_DE: H5.17 R265.1
JTAG_MOD: R387.1 R569.2 ; also on sheet 10
JTAG_PWR: C572.1 H5.2 R264.2
JTAG_RTCK: H5.11 R851.2
JTAG_SRST#: D26.1(K) H5.15 R266.1 R856.2
JTAG_TCK: H5.9 R852.2 ; also on sheet 10
JTAG_TDI: H5.5 R854.1 ; also on sheet 10
JTAG_TDO: H5.13 ; also on sheet 10
JTAG_TMS: H5.7 R267.1 ; also on sheet 10
JTAG_TRST#: H5.3 R855.1 R856.1 ; also on sheet 10
JTAG_VREF: H5.1 R857.1
LCD_CS#: J9.31 R194.1
LCD_DATA0: J9.27 R236.2 SW6.1 ; also on sheet 8
LCD_DATA1: J9.26 R231.2 R238.2 ; also on sheet 8
LCD_DATA2: J9.25 R230.2 R239.2 ; also on sheet 8
LCD_DATA3: J9.24 R229.2 R240.2 ; also on sheet 8
LCD_DATA4: J9.23 R228.1 R241.2 ; also on sheet 8
LCD_DATA5: J9.22 R242.2 SW6.2 ; also on sheet 8
LCD_DATA6: J9.21 R243.2 SW6.3 ; also on sheet 8
LCD_DATA7: J9.20 R244.2 SW6.4 ; also on sheet 8
LCD_DATA8: J9.19 R224.2 R245.2 ; also on sheet 8
LCD_DATA9: J9.18 R223.2 R246.2 ; also on sheet 8
LCD_DATA10: J9.17 R222.2 R247.2 ; also on sheet 8
LCD_DATA11: J9.16 R221.2 R248.2 ; also on sheet 8
LCD_DATA12: J9.15 R220.2 R249.2 ; also on sheet 8
LCD_DATA13: J9.14 R219.2 R250.2 ; also on sheet 8
LCD_DATA14: J9.13 R218.2 R251.2 ; also on sheet 8
LCD_DATA15: J9.12 R217.2 R252.2 ; also on sheet 8
LCD_DATA16: R216.2 R253.2 ; also on sheet 8
LCD_DATA17: R215.2 R254.2 ; also on sheet 8
LCD_DATA18: R214.2 R255.2 ; also on sheet 8
LCD_DATA19: R213.2 R256.2 ; also on sheet 8
LCD_DATA20: R212.2 R257.2 ; also on sheet 8
LCD_DATA21: R211.2 R258.2 ; also on sheet 8
LCD_DATA22: R210.2 R259.2 ; also on sheet 8
LCD_DATA23: R209.2 R260.2 ; also on sheet 8
LCD_DATA/COMND: J9.30 ; also on sheet 8
LCD_IM0: J9.10 R195.2 R197.1
LCD_PWR_EN: D12.1(K) ; also on sheet 10
LCD_RD_E#: J9.28 ; also on sheet 8
LCD_RESET#: R196.1 R807.2 R808.1 ; also on sheet 8
LCD_WR_E#: J9.29 ; also on sheet 8
NVCC_DRAM_1V35: R186.2 TP10.1 U22.14(IN2-) ; also on sheet 4 7
NVCC_DRAM_1V35_SNS: R186.1 U22.15(IN2+) ; also on sheet 4
NVCC_LCD: R209.1 R210.1 R211.1 R212.1 R213.1 R214.1 R215.1 R216.1 R217.1 R218.1 R219.1 R220.1 R221.1 R222.1 R223.1 R224.1 R225.2 R226.2 R227.2 R228.2 R229.1 R230.1 R231.1 R232.2 ; also on sheet 8
PMIC_I2C1_SCL: R875.1 ; also on sheet 4 10
PMIC_I2C1_SDA: R876.2 ; also on sheet 4 10
POR_B: D26.2(A) ; also on sheet 4 10
RES#: J9.11 R196.2
RES_LED1: DA6.4(RK) R205.1
RES_LED2: DA6.3(GK) R206.1
RES_LED3: D15.2(K) R207.1
RXLED: D11.1(K) U20.14(CBUS1)
TOUCH_BUSY: R199.1 ; also on sheet 10
TOUCH_CLOCK: U24.16(DCLK) ; also on sheet 9
TOUCH_CS#: R201.1 ; also on sheet 9
TOUCH_INTR_REQ#: U24.11(PENIRQ#) ; also on sheet 10
TOUCH_MISO: U24.12(DOUT) ; also on sheet 9
TOUCH_MOSI: U24.14(DIN) ; also on sheet 9
TOUCH_X+: C191.2 R198.1 U24.2(X+)
TOUCH_X-: C192.2 R200.1 U24.4(X-)
TOUCH_XL: J9.38 R200.2
TOUCH_XR: J9.36 R198.2
TOUCH_Y+: C193.2 R202.1 U24.3(Y+)
TOUCH_Y-: C194.2 R203.1 U24.5(Y-)
TOUCH_YD: J9.37 R203.2
TOUCH_YU: J9.39 R202.2
TXLED: D10.1(K) U20.7(CBUS2)
UART1_RX_DATA: R167.1 R169.2 ; also on sheet 10
UART1_TX_DATA: R170.2 ; also on sheet 10
USB2ANY_I2C_SCL: H1.9 R875.2
USB2ANY_I2C_SDA: H1.10 R876.1
USBDN: C176.1 R172.2 U20.9(USBDM)
USBDP: C175.1 R171.2 U20.8(USBDP)
USR_B0: R872.2 SW4.2
USR_B1: R873.2 SW5.2
USR_BT0: C195.1 R204.2 R872.1 ; also on sheet 9
USR_BT1: C196.1 R208.2 R873.1 ; also on sheet 9
USR_LED1: R205.2 ; also on sheet 9
USR_LED2: R206.2 ; also on sheet 9
USR_LED3: R207.2 ; also on sheet 9
VREF_TOUCH_C: C189.2 U24.9(VREF)
N20274074: FB5.1 J8.5(GND)
N20274097: J8.4(ID) R173.1
N20280334: D10.2(A) R176.2
N20280345: D11.2(A) R177.2
N20387129: R225.1 SW6.5
N20387131: R226.1 SW6.6
N20387133: R227.1 SW6.7
N20387143: R232.1 SW6.8
N20387145: R575.2 SW7.4
N20387147: R576.2 SW7.3
N20829804: D29.1(K) R266.2

Not connected (* = marked no-connect by the designer): FD1 1*; FD2 1*; FD3 1*; FD4 1*; FD5 1*; FD6 1*; FD7 1*; FD8 1*; FD9 1*; FD10 1*; FD11 1*; FD12 1*; H1 1* 2* 3* 4* 5* 7* 8*; J9 1* 9* 32* 35*; U20 16(CBUS3)*; U22 8(WARNING)* 9(CRITICAL)* 10(PV)* 13(TC)*; U23 8(WARNING)* 9(CRITICAL)* 10(PV)* 13(TC)*; U24 8(AUX)*

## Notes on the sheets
sheet 17
- USB-UART
- Place close to pin 12
- Place C173 close to pin 3 & 10
- NM
- JTAG
- USB2ANY
- NM
- NM
- NM
- NM
- NM
- NM
- NM
- NM
sheet 18
- CURRENT SENSE
- I2C ADDR=0x40
- I2C ADDR=0x41
sheet 19
- LCD
- LCD IO & CORE POWER SWITCHES
- VDDIO for LCD = 1V8.
  3V3 option is given only because of a
  mismatch in datasheet.
  Please refer to data sheet to mount FB6
- Place FB3 & FB4 in tripad
- Place FB5 & FB6 in tripad
- NM
- NM
- VDD_LCD = 2V8 for the part NHD-2.8-240320AF-CSXP-FT
  VDD_LCD = 3V3 for the part NHD-2.4-240320CF-CSXV#-F
- Current Design is for the part NHD-2.4-240320CF-CSXV#-F (No touch)
- NM
- NM
- NM
- NM
- TOUCH CONTROLLER
- NM
- NM
- NM
- NM
- NM
- NM
sheet 20
- FUNCTIONAL SWITCHES AND LED
- GPIO HEADER
- BOOT CONFIGUARTION
- NM
- NM
- NM
- NM
- NM
- NM
- NM
- NM
- NM
- NM
- NM
- NM
- NM
- NM
- NM
- NM
- NM
- NM
- NM
- BT_CFG1[0] is used for SD
  loopback clock selection
- PD (100K)
- PD (100K)
- NOTE: To select boot device as eMMC along
  with the DIP switch change mount R221 with
  10K and no mount R248
- NM
- NM
sheet 21
- MISCELLANEOUS
- GLOBAL FIDUCIALS
- MOUNTING HOLES
- GND TEST POINT
- LOCAL FIDUCIALS
- Ground Test Point Clips
- TOP
- BOTTOM
- TOP
- LCD MOUNTING HOLES
